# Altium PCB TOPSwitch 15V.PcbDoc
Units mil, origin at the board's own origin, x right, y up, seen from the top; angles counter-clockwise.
Board outline 3670 x 2060 mil, 2 copper layers (Top Layer, Bottom Layer); 43 components, 27 nets, 108 pads, 5 vias.
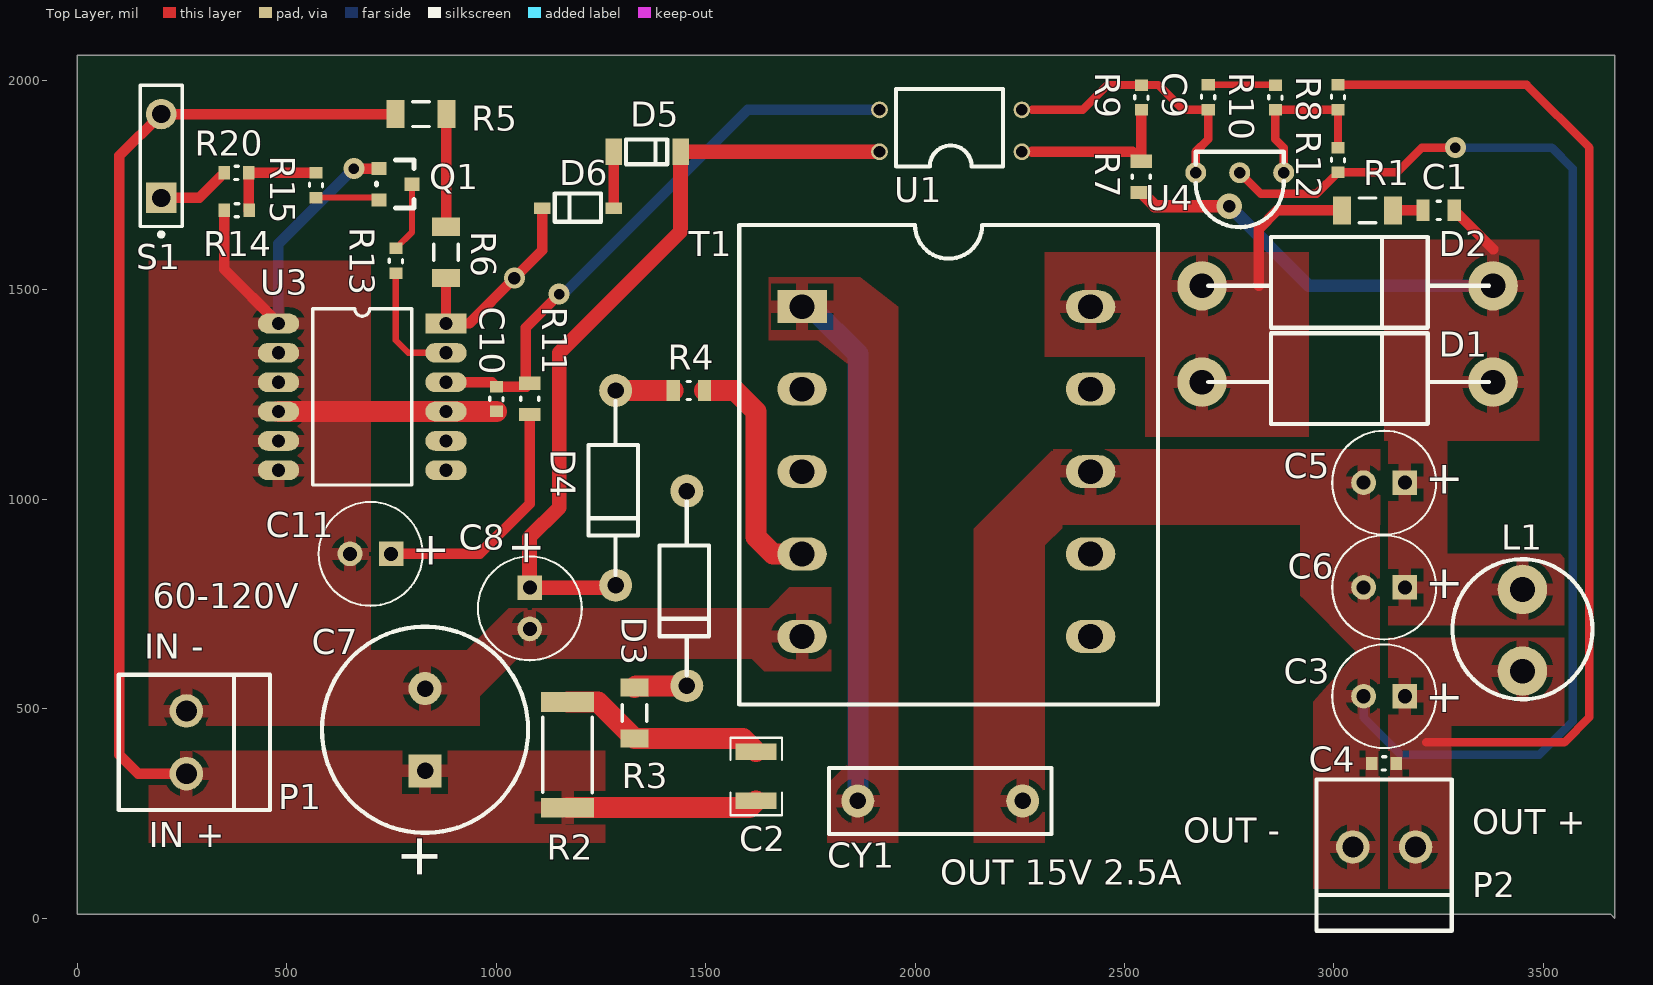
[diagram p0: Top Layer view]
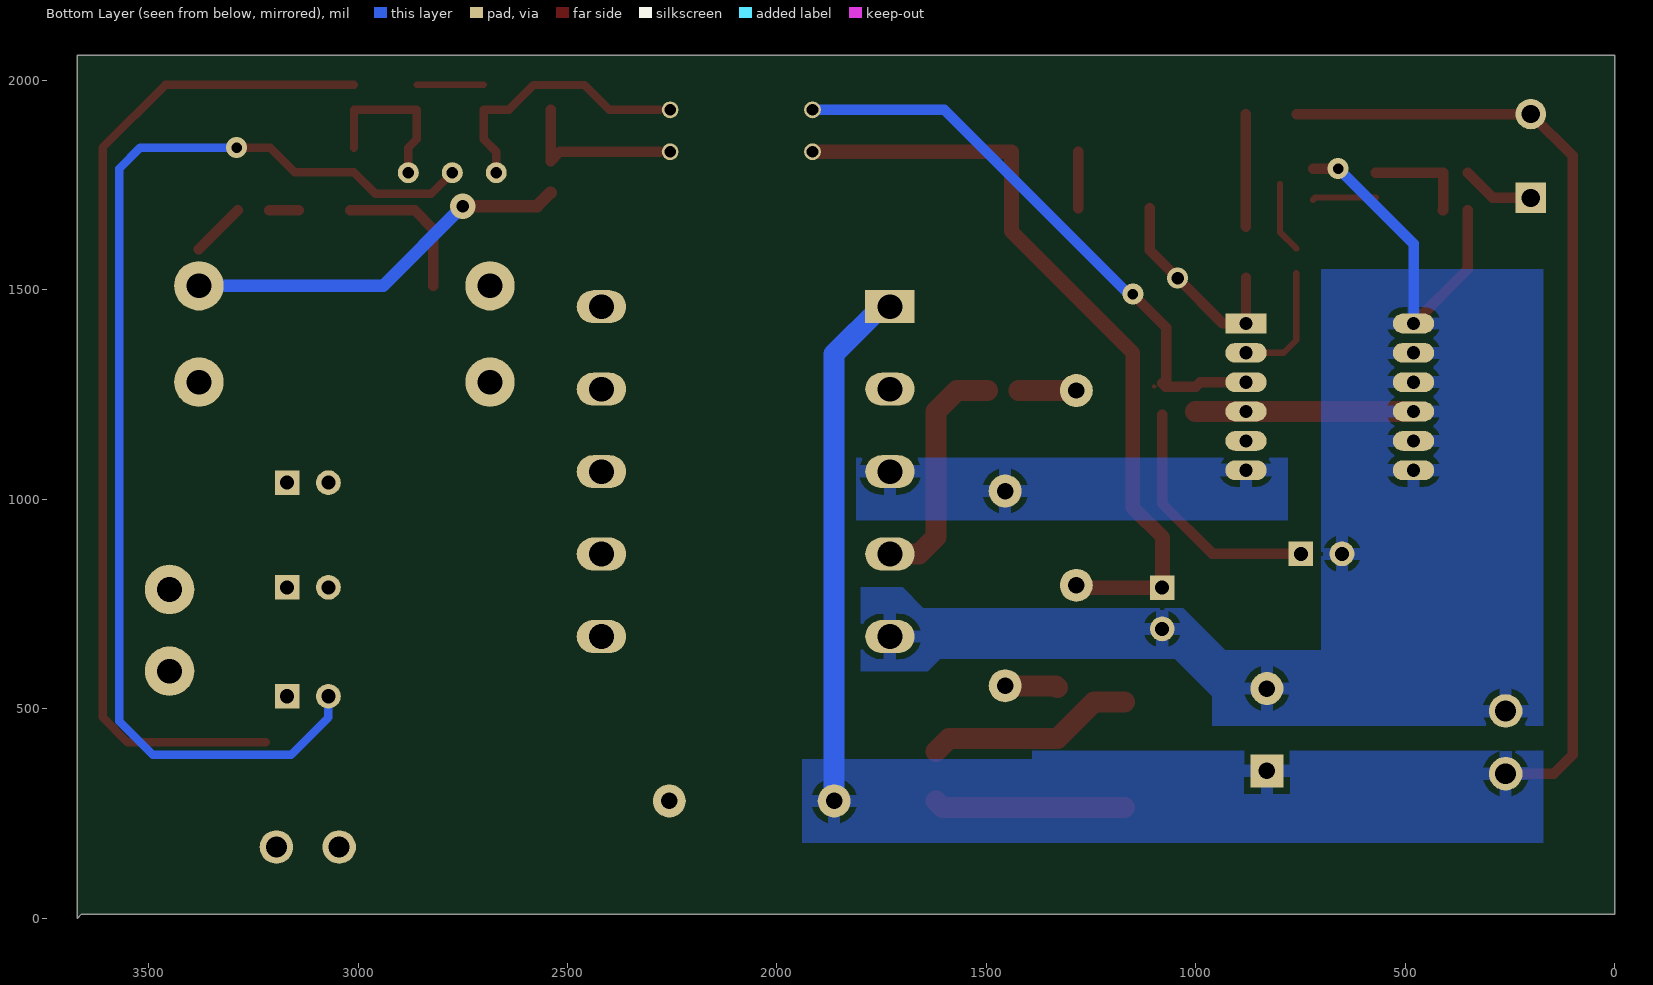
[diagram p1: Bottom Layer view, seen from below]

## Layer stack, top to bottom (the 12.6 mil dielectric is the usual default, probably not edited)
Top Layer: signal copper 1.4
Dielectric: dielectric 12.6, FR-4, Dk 4.8
Bottom Layer: signal copper 1.4

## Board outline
0,2060 3670,2060 3670,0 3660,10 0,10 0,2060

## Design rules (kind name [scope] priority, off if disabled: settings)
Clearance Clearance-Inpoly [Inpoly] p1: gap=15
Clearance Clearance_1 [All] p2: gap=10
ComponentClearance [All] p1 off: gap=10 collisioncheckmode=3 verticalgap=10 showdistances=FALSE
Height [All] p1 off: minheight=0 maxheight=1000 prefheight=500
HoleToHoleClearance [All] p1: gap=4 allowstackedmicrovias=TRUE
MinimumSolderMaskSliver [All] p1: minsoldermaskwidth=4
PlaneConnect [All] p1: planeconnectstyle=Relief reliefexpansion=20 reliefentries=4 reliefconductorwidth=30 reliefairgap=10
PolygonConnect [All] p1: connectstyle=Relief reliefconductorwidth=30 reliefentries=4 polygonreliefangle="90 Angle"
RoutingVias [All] p1: holewidth=28 width=50 viastyle="Through Hole" minholewidth=15 minwidth=25 maxholewidth=50 maxwidth=70
SilkToSilkClearance [All] p1: silktosilkclearance=0
SilkscreenOverComponentPads [All] p1 off: minsilkscreentomaskgap=5
SolderMaskExpansion [All] p1: expansion=4
Width [All] p1: maxlimit=100 minlimit=10 preferedwidth=10
21 further rules are at their usual default settings.

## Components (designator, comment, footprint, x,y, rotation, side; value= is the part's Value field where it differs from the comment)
C1 "100pF  50V" 0805 3250,1690 r0 top
C2 "1000pF 250V" 1210 1620,340 r90 top
C3 "100uF 25V" RB.1/.2 3120,530 r180 top
C4 "100nF 5V" 0603 3120,370 r180 top
C5 "470uF 25V" RB.1/.2 3120,1040 r180 top
C6 "470uF 25V" RB.1/.2 3120,790 r180 top
C7 "33uF 250V" RB.2/.5 830,450 r90 top
C8 "10uF 50V" RB.1/.2 1080,740 r270 top
C9 "100nF 50V" 0603 2700,1960 r90 top
C10 "100nF 50V" 0603 1000,1240 r270 top
C11 "47uF 16V" RB.1/.2 700,870 r180 top
CY1 "2.2nF 250V" RAD-0.4 2060,280 r0 top
D1 "IN5822" DO-201 2850,1180 r0 top
D2 "IN5822" DO-201 2850,1410 r0 top
D3 "FR107(DO-41)" DO-41 1390,890 r270 top
D4 "BAT46W" DO-41 1220,1130 r270 top
D5 "SMCJ15(C)A" DO-213AA 1310,1800 r0 top
D6 "BAT46W" SOD-123 1250,1730 r180 top
L1 "2.2uF 4A" RL822 3450,690 r270 top
P1 "Header 2" ME040-38102 260,420 r0 top
P2 "Header 2" ME040-38102 3120,170 r270 top
Q1 "2N3904" SOT-23 720,1790 r270 top
R1 "110R 1206" 1206 3080,1690 r0 top
R2 "100K 2W" 2512 1170,390 r270 top
R3 "47R 1206" 1206 1330,490 r270 top
R4 "10R 0805" 0805 1460,1260 r180 top
R5 "1.1M  1206" 1206 820,1920 r180 top
R6 "1.1M  1206" 1206 880,1590 r90 top
R7 "560R 0805" 0805 2540,1770 r270 top
R8 "24K 1% 0805" 0603 3010,1960 r90 top
R9 "1K" 0603 2540,1960 r270 top
R10 "4.7K" 0603 2860,1960 r270 top
R11 "6.8R" 0805 1080,1240 r90 top
R12 "4.76K 1% 0805" 0603 3010,1810 r90 top
R13 "6.8K 1%" 0603 760,1570 r270 top
R14 "1K" 0603 380,1690 r0 top
R15 "6.8K 1%" 0603 570,1750 r90 top
R20 "50K" 0603 380,1780 r180 top
S1 "SW-SPST" SPST-2 200,1820 r90 top
T1 "EI28" BYQ 1730,1460 r0 top
U1 "PS2501-1-K-A" 4—DIP 2210,1980 r180 top
U3 "TOP265VG" e-DIP12 480,1420 r0 top
U4 "TL431（TO-92）" TO-92 2720,1880 r0 top

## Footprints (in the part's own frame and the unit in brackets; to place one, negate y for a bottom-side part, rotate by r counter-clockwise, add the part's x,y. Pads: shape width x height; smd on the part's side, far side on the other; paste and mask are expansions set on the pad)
4—DIP [mil]
  round 40 hole 27.56: 1(-45,150) 2(-45,50) 3(295,50) 4(295,150)
  silkscreen extent 0,0 256,185
0603 [mm] "Chip Capacitor, 2-Leads, Body 1.6x0.9mm, IPC Medium Density"
  rect 0.7x0.8 smd: 1(-0.744,0.007) 2(0.757,0.007)
  silkscreen extent -0.1,-0.39 0.12,0.41, body extent -0.8,-0.4 0.8,0.45, height 0.45
0805 [mm] "Chip Resistor, 2-Leads, Body 1.6x0.9mm, IPC Medium Density"
  rect 0.8x1.3 smd: 1(-0.95,0) 2(0.95,0)
  silkscreen extent -0.1,-0.55 0.1,0.55, body extent -0.9,-0.55 0.94,0.55, height 0.45
1206 [mm]
  rect 1.1x1.7 smd: 1(-1.55,0) 2(1.55,0)
  silkscreen extent -0.5,-0.75 0.5,0.75, body extent -1.65,-0.88 1.65,0.87, height 0.55
1210 [mm]
  rect 1x2.5 smd: 1(-1.525,-0.001) 2(1.475,-0.001)
  silkscreen extent -2.39,-1.58 2.31,1.55
2512 [mm]
  rect 1.2x3.2 smd: 1(-3.2,0) 2(3.2,0)
  silkscreen extent -2.29,-1.5 2.29,1.5, body extent -3.68,-1.58 3.68,1.57, height 0.6
BYQ [mm]
  rect 3x2 hole 1.5: 1(0,0)
  oval 3x2 hole 1.5: 2(0,-5) 3(0,-10) 4(0,-15) 5(0,-20) 6(17.5,-20) 7(17.5,-15) 8(17.5,-10) 9(17.5,-5) 10(17.5,0)
  silkscreen extent -3.81,-24.13 21.59,4.95
DO-41 [mm]
  round 2 hole 1: 1(-3.302,1.651) 2(8.509,1.651)
  silkscreen extent -2.67,0 7.87,3
DO-201 [mm]
  round 3 hole 1.5: 1(-4.191,2.54) 2(13.462,2.54)
  silkscreen extent -3.81,0 13.21,5.5
DO-213AA [mil]
  rect 39.37x62.99 smd: 1(-30,30) 2(130,30)
  silkscreen extent 0,0 98,59
e-DIP12 [mm]
  rect 2.5x1.2 hole 0.8: 1(10.16,0)
  oval 2.5x1.2 hole 0.8: 2(10.16,-1.78) 3(10.16,-3.56) 4(10.16,-5.34) 5(10.16,-7.12) 6(10.16,-8.9) 7(0,-8.9) 8(0,-7.12) 9(0,-5.34) 10(0,-3.56) 11(0,-1.78) 12(0,0)
  silkscreen extent 2.08,-9.79 8.08,0.89
ME040-38102 [mil] "http://www.deca.net.cn/list.asp?page=2&class_id=84"
  round 80 hole 50: 1(0,-75) 2(0,75)
  silkscreen extent -161,-161 200,161
RAD-0.4 [mm]
  round 2 hole 1: 1(-5,0) 2(5,0)
  silkscreen extent -6.75,-2 6.75,2
RB.1/.2 [mm] "100uF/16V"
  rect 1.5x1.5 hole 0.85: 1(-1.25,0)
  round 1.5 hole 0.85: 2(1.25,0)
  silkscreen extent -3.15,-3.15 3.15,3.15
RB.2/.5 [mm]
  rect 2x2 hole 1: 1(-2.5,0)
  round 2 hole 1: 2(2.5,0)
  silkscreen extent -6.25,-6.25 6.25,6.25
RL822 [mm]
  round 3 hole 1.5: 1(-2.413,0) 2(2.54,0)
  silkscreen extent -4.25,-4.25 4.25,4.25
SOD-123 [mil]
  rect 39.37x27.56 smd: 1(-30,35) 2(140,35)
  silkscreen extent 0,0 110,67
SOT-23 [mm]
  rect 0.8x0.9 smd: 1(0,0) 2(1.9,0) 3(0.95,2)
  silkscreen extent -0.52,-0.15 2.4,2.13
SPST-2 [mm] "Circuit Breaker; 2 Leads"
  rect 1.85x1.85 hole 1.1: 1(-2.54,0)
  round 1.85 hole 1.1: 2(2.54,0)
  silkscreen extent -4.89,-1.27 4.28,1.27
TO-92 [mm]
  round 1.27 hole 0.7: 1(4.064,-2.54) 2(1.397,-2.54) 3(-1.27,-2.54)
  silkscreen extent -1.27,-5.84 4.06,-1.27

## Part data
C1 C2 C4 C9 C10 CY1: library part CAP1
C3 C5 C6 C7 C8 C11: library part CAP7
D1 D2 D3 D4 D6: library part 1N4001(DO-41)
D5: library part "DIODE SCHOTTKY", "Schottky Diode"
L1: library part INDUCTOR2
P1 P2: "Header, 2-Pin"
Q1: "NPN General Purpose Amplifier"
R1 R2 R3 R4 R5 R6 R7 R8 R9 R10 R11 R12 R13 R14 R15 R20: library part RESISTOR-S
S1: "Single-Pole, Single-Throw Switch"
T1: library part "INDUCTOR ISOLATED"
U1: library part PC817-B
U4: library part TL431(TO-92)

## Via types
v1: diameter 50, hole 25, Top Layer to Bottom Layer, 2 vias
v2: diameter 50, hole 25, Top Layer to Bottom Layer, tented both sides, 1 vias
v3: diameter 60, hole 30, Top Layer to Bottom Layer, tented both sides, 1 vias
v4: diameter 50, hole 30, Top Layer to Bottom Layer, 1 vias

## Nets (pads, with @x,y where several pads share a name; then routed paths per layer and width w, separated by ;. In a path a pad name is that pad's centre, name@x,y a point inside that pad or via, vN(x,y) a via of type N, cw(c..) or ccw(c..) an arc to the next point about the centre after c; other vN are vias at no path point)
NetC1_1: C1.1 R1.2 | length 71.6
  Top Layer w25: R1.2 C1.1
NetC1_2: C1.2 C5.1 C6.1 D1.2 D2.2 L1.1 R7.2 | length 1063.2
  Top Layer w25: C1.2 3380,1597.4
  Top Layer w30: R7.2 2572.6,1700 v3(2750,1700)
  Bottom Layer w30: v3(2750,1700) 2940,1510 D2.2
NetC2_1: C2.1 C7.1 CY1.1 P1.1 R2.2 R5.2 S1.2 T1.1 | length 4012.6
  Top Layer w25: P1.1 145,345 100,390 100,1820 S1.2 R5.2
  Top Layer w50: R2.2 1604.12,264.02 C2.1
  Bottom Layer w50: T1.1 1750,1460 1863.15,1346.85 CY1.1
NetC2_2: C2.2 R2.1 R3.2 | length 498.9
  Top Layer w50: R2.1 1242.99,515.98 R3.2 1589.13,428.98 C2.2
NetC3_1: C3.1 C4.1 L1.2 P2.2 R8.2 | length 2437.2
  Top Layer w20: R8.2 3460.22,1989.78 3610,1840 3610,480 3550,420 3220,420
NetC3_2: C3.2 C4.2 C5.2 C6.2 CY1.2 P2.1 R12.1 T1.8 U4.2 | length 2824.8
  Top Layer w20: U4.2 2825,1730 2958.99,1730 R12.1 3150.73,1780.73 3210,1840 v1(3290,1840)
  Top Layer w50: T1.8@2416.3,1066.3 T1.8
  Bottom Layer w20: C3.2 3070.79,479.21 3160,390 3490,390 3570,470 3570,1790 3520,1840 v1(3290,1840)
NetC7_2: C7.2 C8.2 C10.2 C11.2 P1.2 Q1.1 R14.1 T1.5 U3.4 U3.7 U3.8 U3.9 U3.10 U3.11 U3.12 | length 1348.9
  Top Layer w15: U3.4 U3.4@880.45,1210.22
  Top Layer w25: R14.1 350.73,1549.27 U3.12 ; v2(660,1790) Q1.1
  Top Layer w50: U3.9 U3.4 ; U3.4@880.45,1210.22 C10.2
  Bottom Layer w25: U3.12 480,1610 v2(660,1790)
NetC8_1: C8.1 D4.2 D5.2 U1.4 | length 1873.4
  Top Layer w25: D4.2@1279.21,789.21 D4.2
  Top Layer w35: D4.2@1279.21,789.21 1079.21,789.21 1079.21,909.21 1150,980 1150,1350 1440,1640 D5.2 U1.4
NetC9_1: C9.1 R9.1 U1.2 U4.3 | length 631.6
  Top Layer w20: 2280,1930 2400,1930 2459.27,1989.27 R9.1 2580.73,1989.27 2639.27,1930.73 C9.1 2699.72,1859.72 2670,1830 U4.3
NetC9_2: C9.2 R10.1 | length 160
  Top Layer w15: C9.2 R10.1@2859.77,1989.78
NetC10_1: C10.1 R11.2 U1.3 U3.3 | length 1389.3
  Top Layer w10: R11.2@1099.21,1269.27 R11.2@1099.72,1269.78
  Top Layer w25: U3.3 989.71,1279.84 C10.1 1071.87,1269.27 R11.2 ; R11.2@1070,1280 1070,1410 v1(1150,1490)
  Bottom Layer w25: v1@1159.72,1489.72 1600,1930 U1.3
NetC11_1: C11.1 R11.1 | length 593.1
  Top Layer w25: C11.1 960,870 1080,990 R11.1
NetD1_1: D1.1 D2.1 R1.1 T1.10 | length 352.6
  Top Layer w25: 2820,1510 2820,1645 2864.99,1689.99 R1.1
NetD3_1: D3.1 T1.3 U3.6
NetD3_2: D3.2 R3.1 | length 126.7
  Top Layer w50: R3.1 1333.97,555 D3.2
NetD4_1: D4.1 R4.2 | length 137.6
  Top Layer w50: D4.1 R4.2
NetD5_1: D5.1 D6.1 | length 135
  Top Layer w25: D6.1 D5.1
NetD6_2: D6.2 R6.1 U3.1 | length 511.5
  Top Layer w25: R6.1 U3.1 935,1420 v4(1043.13,1528.13) 1110,1595 D6.2
NetQ1_2: Q1.2 R15.1 | length 152.6
  Top Layer w15: R15.1 714.47,1720.73 Q1.2
NetQ1_3: Q1.3 R13.1 | length 169.3
  Top Layer w15: R13.1 798.74,1637.73 Q1.3
NetR4_1: R4.1 T1.4 | length 570.1
  Top Layer w50: R4.1 1570,1260 1620,1210 1620,910 1660.55,869.45 T1.4
NetR5_1: R5.1 R6.2 | length 269.4
  Top Layer w25: R6.2 881.02,1652.04 R5.1
NetR7_1: R7.1 R9.2 U1.1 | length 392.1
  Top Layer w25: 2280,1830 2517.96,1830 2540.28,1807.68 R9.2
NetR8_1: R8.1 R10.2 R12.2 U4.1 | length 399
  Top Layer w10: R8.1@3009.21,1930.22 R8.1
  Top Layer w20: U4.1 2880,1840 2860.28,1859.72 R10.2 R8.1@3009.21,1930.22 ; R12.2 R8.1
NetR13_2: R13.2 U3.2 | length 292.6
  Top Layer w15: R13.2 760.28,1379.72 790.08,1349.92 U3.2
NetR14_2: R14.2 R15.2 R20.1 | length 250.1
  Top Layer w25: R14.2 409.27,1690.79 R20.1 569.66,1779.72 R15.2
NetR20_2: R20.2 S1.1 | length 175
  Top Layer w25: S1.1 290.5,1720 R20.2
pads on no net: T1.2 T1.6 T1.7 T1.9 U3.5

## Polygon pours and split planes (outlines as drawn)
NetC7_2 on Top Layer "Top Layer-No Net" (solid, remove dead copper): 700,460 700,640 930,640 1030,740 1040,740 1650,740 1700,790 1750,790 1800,790 1800,590 1640,590 1610,620 1050,620 960,530 960,460 700,460
NetC3_2 on Top Layer "Top Layer-No Net" (solid, pour order 1007): 2330,1120 3110,1120 3110,940 2350.8,940 2330,960 2330,940
NetD1_1 on Top Layer "Top Layer-No Net" (solid, pour order 1000): 2310,1590 2940,1590 2940,1340 2310,1340
NetD1_1 on Top Layer "Top Layer-No Net" (solid, pour order 1001): 2550,1380 2550,1150 2940,1150 2940,1367.89 2930.25,1380
NetC1_2 on Top Layer "Top Layer-No Net" (solid, remove dead copper, pour order 1002): 3120,1620 3490,1620 3490,1140 3120,1140
NetC1_2 on Top Layer "Top Layer-No Net" (solid, pour order 1003): 3130,1140 3130,700 3270,700 3270,1140
NetC1_2 on Top Layer "Top Layer-No Net" (solid, pour order 1004): 3270,700 3550,700 3550,860 3540,870 3270,870
NetC3_1 on Top Layer "Top Layer-No Net" (solid, pour order 1005): 3130,670 3550,670 3550,460 3130,460
NetC3_1 on Top Layer "Top Layer-No Net" (solid, remove dead copper, pour order 1006): 3130,470 3130,70.22 3280,70.22 3280,470
NetC3_2 on Top Layer "Top Layer-No Net" (solid, pour order 1008): 3109.8,940 3109.8,640.2 3110,640 3050,640 2930,760 2920,770 2920,940
NetC3_2 on Top Layer "Top Layer-No Net" (solid, pour order 1009): 3109.8,639.98 3109.8,70.22 3110,70 2950,70 2950,517.04 3049.8,628.58 3049.8,640.2
NetC2_1 on Top Layer "Top Layer-No Net" (solid, pour order 1010): 170,400 1260,400 1260,180 181.98,180 170,180
NetC2_1 on Top Layer "Top Layer-No Net" (solid, remove dead copper, pour order 1000): 1840,180 1840,1360 1840,1390 1900,1460 1960,1460 1960,180
NetC2_1 on Top Layer "Top Layer-No Net" (solid, remove dead copper, pour order 1001): 1960,1460 1869.58,1530 1650,1530 1650,1380 1766.25,1380 1856.67,1310 1869.58,1300
NetC7_2 on Top Layer "Top Layer-No Net" (solid, remove dead copper, pour order 1002): 170,1570 700,1570 700,460 170,460
NetC3_2 on Top Layer "Top Layer-No Net" (solid, remove dead copper, pour order 1003): 2330,1120 2140,930 2140,180 2310,180 2310,890 2350.8,930.8 2350.8,940
NetC2_1 on Top Layer "Top Layer-No Net" (solid, remove dead copper, pour order 1004): 1840,400 1840,370 1790,320 1790,180 1840,180
NetC7_2 on Bottom Layer "Top Layer-No Net" (solid, remove dead copper): 170,710 700,710 700,640 930,640 1030,740 1650,740 1700,790 1800,790 1800,590 1640,590 1610,620 1050,620 1040,610 960,530 960,460 170,460 170,710
NetC2_1 on Bottom Layer "Top Layer-No Net" (solid, remove dead copper, pour order 1005): 1390,380 1940,380 1940,180 1390,180
NetC2_1 on Bottom Layer "Top Layer-No Net" (solid, remove dead copper, pour order 1004): 170,400 1390,400 1390,180 170,180
NetC7_2 on Bottom Layer "Top Layer-No Net" (solid, remove dead copper, pour order 1013): 170,710 170,1550 700,1550 700,710
NetD3_1 on Bottom Layer "Top Layer-No Net" (solid, pour order 1014): 780,1100 1810,1100 1810,950 780,950

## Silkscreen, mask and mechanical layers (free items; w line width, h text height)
Top Overlay:
  text "60-120V" at 180,740 h60
  text "IN -" at 160,620 h60
  text "OUT +" at 3330,200 h60
  text "OUT -" at 2640,180 h60
  text "IN +" at 170,170 h60
  text "OUT 15V 2.5A" at 2060,80 h60
Mechanical 1:
  circle w10: c47.64,-10 r22.36
  circle w10: c102.6,-10 r22.36
  circle w10: c212.53,-10 r22.36
  circle w10: c157.56,-10 r22.36
  circle w10: c377.42,-10 r22.36
  circle w10: c432.38,-10 r22.36
  circle w10: c322.45,-10 r22.36
  circle w10: c267.49,-10 r22.36
  circle w10: c597.27,-10 r22.36
  circle w10: c652.23,-10 r22.36
  circle w10: c542.3,-10 r22.36
  circle w10: c487.34,-10 r22.36
  circle w10: c1146.9,-10 r22.36
  circle w10: c1201.86,-10 r22.36
  circle w10: c1311.78,-10 r22.36
  circle w10: c1256.82,-10 r22.36
  circle w10: c927.04,-10 r22.36
  circle w10: c982.01,-10 r22.36
  circle w10: c1091.93,-10 r22.36
  circle w10: c1036.97,-10 r22.36
  circle w10: c817.12,-10 r22.36
  circle w10: c872.08,-10 r22.36
  circle w10: c762.16,-10 r22.36
  circle w10: c707.19,-10 r22.36
  circle w10: c2026.3,-10 r22.36
  circle w10: c2081.26,-10 r22.36
  circle w10: c2191.19,-10 r22.36
  circle w10: c2136.23,-10 r22.36
  circle w10: c2356.08,-10 r22.36
  circle w10: c2411.04,-10 r22.36
  circle w10: c2301.11,-10 r22.36
  circle w10: c2246.15,-10 r22.36
  circle w10: c2575.93,-10 r22.36
  circle w10: c2630.89,-10 r22.36
  circle w10: c2520.97,-10 r22.36
  circle w10: c2466,-10 r22.36
  circle w10: c1806.45,-10 r22.36
  circle w10: c1861.41,-10 r22.36
  circle w10: c1971.34,-10 r22.36
  circle w10: c1916.37,-10 r22.36
  circle w10: c1586.6,-10 r22.36
  circle w10: c1641.56,-10 r22.36
  circle w10: c1751.49,-10 r22.36
  circle w10: c1696.52,-10 r22.36
  circle w10: c1476.67,-10 r22.36
  circle w10: c1531.63,-10 r22.36
  circle w10: c1421.71,-10 r22.36
  circle w10: c1366.75,-10 r22.36
  circle w10: c3620.22,-10 r22.36
  circle w10: c2740.82,-10 r22.36
  circle w10: c2685.85,-10 r22.36
  circle w10: c3345.41,-10 r22.36
  circle w10: c3400.37,-10 r22.36
  circle w10: c3510.3,-10 r22.36
  circle w10: c3455.33,-10 r22.36
  circle w10: c3565.26,-10 r22.36
  circle w10: c3125.56,-10 r22.36
  circle w10: c3180.52,-10 r22.36
  circle w10: c3290.44,-10 r22.36
  circle w10: c3235.48,-10 r22.36
  circle w10: c2905.7,-10 r22.36
  circle w10: c2960.67,-10 r22.36
  circle w10: c3070.59,-10 r22.36
  circle w10: c3015.63,-10 r22.36
  circle w10: c2795.78,-10 r22.36
  circle w10: c2850.74,-10 r22.36
  lines w20: 0,0 0,2060 3660,2060 3660,0 0,0

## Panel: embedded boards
"..\TOPSwitch 15V 1A\TOPSwitch 15V 1A.PcbDoc" at 0,-2260, 1 rows x 1 columns, spacing 2500 x 1500, rotation 0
